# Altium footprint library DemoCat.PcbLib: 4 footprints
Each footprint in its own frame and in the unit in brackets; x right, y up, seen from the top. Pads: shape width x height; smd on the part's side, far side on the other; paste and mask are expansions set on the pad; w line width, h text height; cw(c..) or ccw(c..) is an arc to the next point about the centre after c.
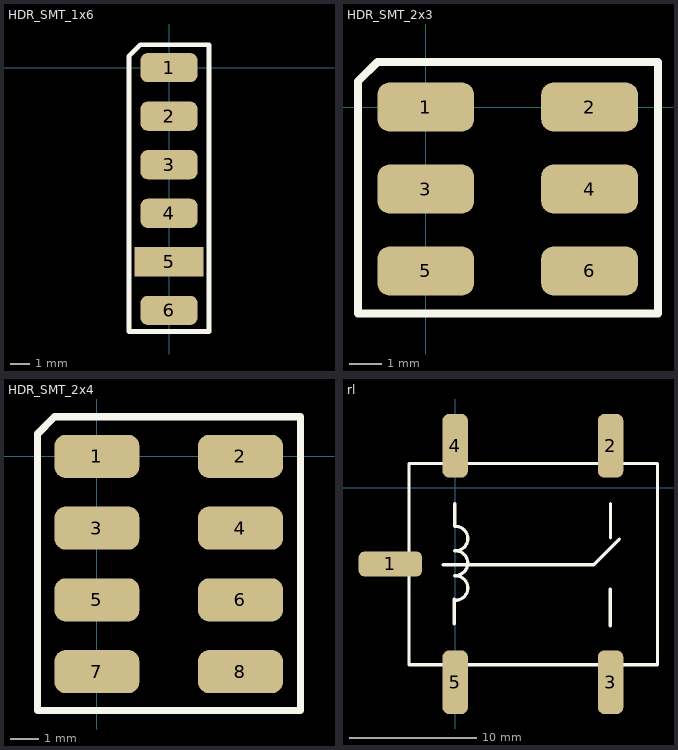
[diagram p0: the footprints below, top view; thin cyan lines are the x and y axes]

## HDR_SMT_1x6 [mil]
pads (6):
  rrect50% 118.11x60 smd: 1(0,0) 2(0,-100) 3(0,-200) 4(0,-300) 6(0,-500)
  rect 141.73x60 smd: 5(0,-400)
Top Overlay:
  lines w10: -82.68,-543.31 -82.68,23.62 -59.06,47.24 0,47.24 82.68,47.24 82.68,-543.31 -82.68,-543.31

## HDR_SMT_2x3 [mil]
pads (6):
  rrect50% 118.11x60 smd: 1(0,0) 2(200,0) 3(0,-100) 4(200,-100) 5(0,-200) 6(200,-200)
Top Overlay:
  lines w10: -82.68,-251.97 -82.68,31.5 -59.06,55.12 0,55.12 200.79,55.12 283.46,55.12 283.46,-251.97 129.92,-251.97 -82.68,-251.97

## HDR_SMT_2x4 [mil]
pads (8):
  rrect50% 118.11x60 smd: 1(0,0) 2(200,0) 3(0,-100) 4(200,-100) 5(0,-200) 6(200,-200) 7(0,-300) 8(200,-300)
Top Overlay:
  lines w10: -82.68,-354.33 -82.68,-251.97 -82.68,31.5 -59.06,55.12 0,55.12 200.79,55.12 283.46,55.12 283.46,-251.97 283.46,-354.33 129.92,-354.33 -82.68,-354.33

## rl [mm]
pads (5):
  rrect50% 5x2 smd: 1(-5.1,-6)
  rrect50% 2x5 smd: 2(12.217,3.3) 3(12.217,-15.3) 4(0,3.3) 5(0,-15.3)
Top Overlay:
  lines w0.254: -0.965,-6.058 10.897,-6.058 12.916,-4.039 ; -0.076,-10.706 -0.076,-8.776 ; -0.051,-8.852 ccw(c0.021,-7.887) -0.04,-6.922 ; -0.051,-6.896 ccw(c0.021,-5.932) -0.04,-4.966 ; -0.051,-4.966 ccw(c0.021,-4.001) -0.04,-3.036 -0.04,-1.243 ; 12.192,-10.884 12.192,-7.988 ; 12.217,-3.95 12.217,-1.257 ; -3.632,-13.919 15.9,-13.919 15.9,1.905 -3.632,1.905 -3.632,-13.919
3D body "User Library-SONGLE Relay SRU-12VDC-SL-C.step": height 15.3, standoff -5, extent -3.403,-13.906 15.697,1.594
